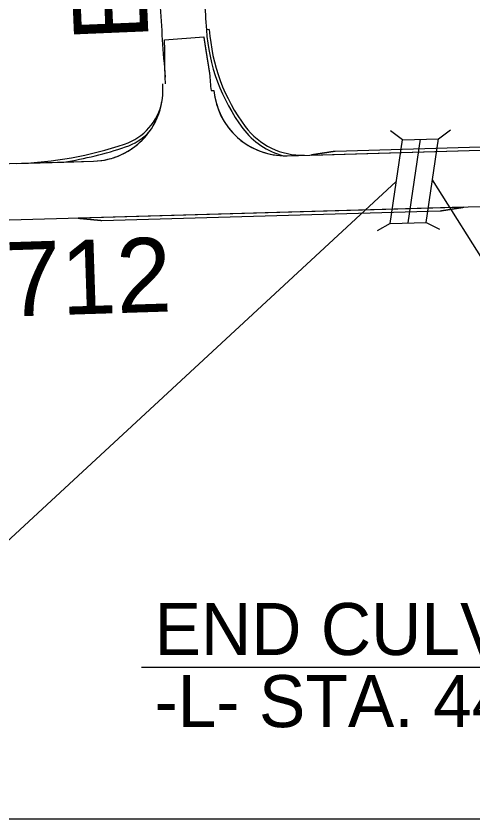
# Model space of a CAD drawing. Extents: x 1750553 to 1763838, y 734059 to 742526.
# Drawn here: x 1758820 to 1759127, y 736593 to 737133 of the extents above; entities that cross this region are included whole.
import ezdxf

# ---------------------------------------------------------------- set-up
doc = ezdxf.new("R2010")
doc.units = 0
for name, color, linetype in [('ENG SEALS CELL', 7, 'Continuous'), ('Old_Level_2', 7, 'Continuous'), ('Prop Drainage Structure Box Reinforced Concrete', 7, 'Continuous'), ('Sheet PE Seal Cell', 7, 'Continuous')]:
    doc.layers.add(name, color=color, linetype=linetype)

msp = doc.modelspace()

# ---------------------------------------------------------------- linework, layer by layer
at = {"layer": 'ENG SEALS CELL'}
msp.add_lwpolyline([(1758065.14, 737642.98), (1758094.96, 736592.98), (1759395.48, 736592.98), (1759372.29, 737409.84), (1759305.61, 737409.84), (1759305.61, 737642.98)], close=True, dxfattribs=at)
at = {"layer": 'Old_Level_2'}
for p, q in [((1758920.2, 737117), (1758946.57, 737118.84)), ((1758946.57, 737118.84), (1758946.53, 737118.84)), ((1758950.25, 737123.84), (1758948.26, 737123.71)), ((1758920.9, 737087.39), (1758920.53, 737091.81)), ((1758951.39, 737082.76), (1758953.38, 737082.93)), ((1759002.57, 737039.01), (1760207.16, 737073.22)), ((1759018.84, 737039.47), (1759254.68, 737046.17)), ((1759238.63, 737047.72), (1759034.78, 737041.93)), ((1759002.57, 737039.01), (1759014.23, 737039.34)), ((1757497.71, 736996.28), (1758872.43, 737035.32)), ((1760223.41, 737035.66), (1757498.72, 736958.29)), ((1758820.95, 737033.85), (1758852.5, 737034.75)), ((1758852.5, 737034.75), (1758872.43, 737035.32)), ((1758872.54, 737035.32), (1758872.64, 737035.32)), ((1759121.42, 737004.37), (1758862.05, 736997.01)), ((1758878.1, 736995.46), (1759105.48, 737001.92))]:
    msp.add_line(p, q, dxfattribs=at)
msp.add_lwpolyline([(1758920.2, 737117), (1758946.53, 737118.84), (1758946.57, 737118.84)], dxfattribs=at)
for centre, radius, start, end in [((1761377.64, 737289.03), 2465, 183.41974, 184.58755), ((1761377.64, 737289.03), 2435, 183.41974, 183.89301), ((1759072.97, 737132.19), 125, 183.893, 216.7448), ((1759072.97, 737132.19), 125, 183.893, 216.7448), ((1759072.97, 737132.19), 123, 183.893, 216.7448), ((1761377.64, 737289.03), 2435, 184.58904, 184.85937), ((1761377.64, 737289.03), 2435, 184.58904, 184.85937), ((1758871.07, 737083.3), 48, 271.6265, 4.6921), ((1759001.21, 737086.99), 48, 184.8594, 271.6265), ((1759001.21, 737086.99), 48, 184.8594, 268.5577), ((1758881.14, 737082.81), 38, 288.6709, 348.7824), ((1758871.07, 737083.3), 48, 323.5301, 350.5475), ((1758871.07, 737083.3), 48, 271.6265, 323.5301), ((1758881.14, 737082.81), 40, 288.6709, 315.4916), ((1758881.14, 737082.81), 40, 288.6709, 315.4916), ((1759012.87, 737087.32), 50, 216.7448, 255.0869), ((1759012.87, 737087.32), 50, 216.7448, 255.0869), ((1759012.87, 737087.32), 48, 216.7448, 271.6265), ((1758813.91, 737281.75), 248, 271.6265, 288.6709), ((1758813.91, 737281.75), 250, 278.8788, 288.6709), ((1758813.91, 737281.75), 250, 278.8788, 288.6709), ((1759001.21, 737086.99), 48, 268.5577, 271.6265)]:
    msp.add_arc(centre, radius, start, end, dxfattribs=at)
for points in [[(1758946.53, 737118.84), (1758946.63, 737118.17), (1758946.68, 737117.84), (1758946.73, 737117.51), (1758946.78, 737117.17), (1758946.84, 737116.84), (1758946.89, 737116.51), (1758946.94, 737116.17), (1758946.99, 737115.84), (1758947.04, 737115.51), (1758947.09, 737115.17), (1758947.15, 737114.84), (1758947.2, 737114.51), (1758947.25, 737114.17), (1758947.3, 737113.84), (1758947.35, 737113.51), (1758947.4, 737113.17), (1758947.46, 737112.84), (1758947.51, 737112.51), (1758947.56, 737112.18), (1758947.61, 737111.84), (1758947.67, 737111.51), (1758947.72, 737111.18), (1758947.77, 737110.84), (1758947.82, 737110.51), (1758947.87, 737110.18), (1758947.93, 737109.84), (1758947.98, 737109.51), (1758948.03, 737109.18), (1758948.08, 737108.85), (1758948.14, 737108.51), (1758948.19, 737108.18), (1758948.24, 737107.85), (1758948.3, 737107.51), (1758948.35, 737107.18), (1758948.4, 737106.85), (1758948.45, 737106.51), (1758948.51, 737106.18), (1758948.56, 737105.85), (1758948.61, 737105.52), (1758948.67, 737105.18), (1758948.72, 737104.85), (1758948.77, 737104.52), (1758948.83, 737104.19), (1758948.88, 737103.85), (1758948.93, 737103.52), (1758948.99, 737103.19), (1758949.04, 737102.85), (1758949.09, 737102.52), (1758949.15, 737102.19), (1758949.2, 737101.86), (1758949.25, 737101.52), (1758949.31, 737101.19), (1758949.36, 737100.86), (1758949.41, 737100.52), (1758949.47, 737100.19), (1758949.52, 737099.86), (1758949.57, 737099.53), (1758949.63, 737099.19), (1758949.68, 737098.86), (1758949.74, 737098.53), (1758949.79, 737098.2), (1758949.84, 737097.86), (1758949.9, 737097.53), (1758949.95, 737097.2), (1758950.01, 737096.87), (1758950.06, 737096.53), (1758950.12, 737096.2), (1758950.17, 737095.87), (1758950.22, 737095.54), (1758950.28, 737095.2), (1758950.33, 737094.87), (1758950.39, 737094.54), (1758950.44, 737094.21)], [(1758946.53, 737118.84), (1758946.63, 737118.17), (1758946.68, 737117.84), (1758946.73, 737117.51), (1758946.78, 737117.17), (1758946.84, 737116.84), (1758946.89, 737116.51), (1758946.94, 737116.17), (1758946.99, 737115.84), (1758947.04, 737115.51), (1758947.09, 737115.17), (1758947.15, 737114.84), (1758947.2, 737114.51), (1758947.25, 737114.17), (1758947.3, 737113.84), (1758947.35, 737113.51), (1758947.4, 737113.17), (1758947.46, 737112.84), (1758947.51, 737112.51), (1758947.56, 737112.18), (1758947.61, 737111.84), (1758947.67, 737111.51), (1758947.72, 737111.18), (1758947.77, 737110.84), (1758947.8, 737110.62)], [(1758920.53, 737091.81), (1758920.53, 737092.15), (1758920.52, 737092.49), (1758920.52, 737092.83), (1758920.51, 737093.17), (1758920.5, 737093.51), (1758920.5, 737093.85), (1758920.49, 737094.19), (1758920.49, 737094.53), (1758920.48, 737094.87), (1758920.48, 737095.21), (1758920.47, 737095.55), (1758920.46, 737095.89), (1758920.46, 737096.23), (1758920.45, 737096.57), (1758920.45, 737096.91), (1758920.44, 737097.25), (1758920.44, 737097.59), (1758920.43, 737097.93), (1758920.43, 737098.27), (1758920.42, 737098.62), (1758920.42, 737098.96), (1758920.41, 737099.3), (1758920.4, 737099.64), (1758920.4, 737099.98), (1758920.39, 737100.32), (1758920.39, 737100.66), (1758920.38, 737101), (1758920.38, 737101.34), (1758920.37, 737101.68), (1758920.37, 737102.02), (1758920.37, 737102.36), (1758920.36, 737102.7), (1758920.36, 737103.04), (1758920.35, 737103.38), (1758920.35, 737103.72), (1758920.34, 737104.06), (1758920.34, 737104.4), (1758920.33, 737104.74), (1758920.33, 737105.08), (1758920.32, 737105.42), (1758920.32, 737105.76), (1758920.32, 737106.1), (1758920.31, 737106.44), (1758920.31, 737106.79), (1758920.3, 737107.13), (1758920.3, 737107.47), (1758920.3, 737107.81), (1758920.29, 737108.15), (1758920.29, 737108.49), (1758920.28, 737108.83), (1758920.28, 737109.17), (1758920.28, 737109.51), (1758920.27, 737109.85), (1758920.27, 737110.19), (1758920.27, 737110.53), (1758920.26, 737110.87), (1758920.26, 737111.21), (1758920.25, 737111.55), (1758920.25, 737111.89), (1758920.25, 737112.23), (1758920.24, 737112.57), (1758920.24, 737112.91), (1758920.24, 737113.25), (1758920.23, 737113.59), (1758920.23, 737113.93), (1758920.23, 737114.27), (1758920.23, 737114.61), (1758920.22, 737114.95), (1758920.22, 737115.29), (1758920.22, 737115.64), (1758920.21, 737115.98), (1758920.21, 737116.32), (1758920.2, 737117)], [(1758920.29, 737108.6), (1758920.28, 737108.83), (1758920.28, 737109.17), (1758920.28, 737109.51), (1758920.27, 737109.85), (1758920.27, 737110.19), (1758920.27, 737110.53), (1758920.26, 737110.87), (1758920.26, 737111.21), (1758920.25, 737111.55), (1758920.25, 737111.89), (1758920.25, 737112.23), (1758920.24, 737112.57), (1758920.24, 737112.91), (1758920.24, 737113.25), (1758920.23, 737113.59), (1758920.23, 737113.93), (1758920.23, 737114.27), (1758920.23, 737114.61), (1758920.22, 737114.95), (1758920.22, 737115.29), (1758920.22, 737115.64), (1758920.21, 737115.98), (1758920.21, 737116.32), (1758920.2, 737117)], [(1758920.4, 737100.2), (1758920.39, 737100.32), (1758920.39, 737100.66), (1758920.38, 737101), (1758920.38, 737101.34), (1758920.37, 737101.68), (1758920.37, 737102.02), (1758920.37, 737102.36), (1758920.36, 737102.7), (1758920.36, 737103.04), (1758920.35, 737103.38), (1758920.35, 737103.72), (1758920.34, 737104.06), (1758920.34, 737104.4), (1758920.33, 737104.74), (1758920.33, 737105.08), (1758920.32, 737105.42), (1758920.32, 737105.76), (1758920.32, 737106.1), (1758920.31, 737106.44), (1758920.31, 737106.79), (1758920.3, 737107.13), (1758920.3, 737107.47), (1758920.3, 737107.81), (1758920.29, 737108.15), (1758920.29, 737108.49), (1758920.29, 737108.6)], [(1758947.8, 737110.62), (1758947.82, 737110.51), (1758947.87, 737110.18), (1758947.93, 737109.84), (1758947.98, 737109.51), (1758948.03, 737109.18), (1758948.08, 737108.85), (1758948.14, 737108.51), (1758948.19, 737108.18), (1758948.24, 737107.85), (1758948.3, 737107.51), (1758948.35, 737107.18), (1758948.4, 737106.85), (1758948.45, 737106.51), (1758948.51, 737106.18), (1758948.56, 737105.85), (1758948.61, 737105.52), (1758948.67, 737105.18), (1758948.72, 737104.85), (1758948.77, 737104.52), (1758948.83, 737104.19), (1758948.88, 737103.85), (1758948.93, 737103.52), (1758948.99, 737103.19), (1758949.04, 737102.85), (1758949.09, 737102.52), (1758949.11, 737102.41)], [(1758920.53, 737091.87), (1758920.53, 737092.15), (1758920.52, 737092.49), (1758920.52, 737092.83), (1758920.51, 737093.17), (1758920.5, 737093.51), (1758920.5, 737093.85), (1758920.49, 737094.19), (1758920.49, 737094.53), (1758920.48, 737094.87), (1758920.48, 737095.21), (1758920.47, 737095.55), (1758920.46, 737095.89), (1758920.46, 737096.23), (1758920.45, 737096.57), (1758920.45, 737096.91), (1758920.44, 737097.25), (1758920.44, 737097.59), (1758920.43, 737097.93), (1758920.43, 737098.27), (1758920.42, 737098.62), (1758920.42, 737098.96), (1758920.41, 737099.3), (1758920.4, 737099.64), (1758920.4, 737099.98), (1758920.4, 737100.2)], [(1758949.11, 737102.41), (1758949.15, 737102.19), (1758949.2, 737101.86), (1758949.25, 737101.52), (1758949.31, 737101.19), (1758949.36, 737100.86), (1758949.41, 737100.52), (1758949.47, 737100.19), (1758949.52, 737099.86), (1758949.57, 737099.53), (1758949.63, 737099.19), (1758949.68, 737098.86), (1758949.74, 737098.53), (1758949.79, 737098.2), (1758949.84, 737097.86), (1758949.9, 737097.53), (1758949.95, 737097.2), (1758950.01, 737096.87), (1758950.06, 737096.53), (1758950.12, 737096.2), (1758950.17, 737095.87), (1758950.22, 737095.54), (1758950.28, 737095.2), (1758950.33, 737094.87), (1758950.39, 737094.54), (1758950.44, 737094.21)], [(1759024.15, 737040.29), (1759024.01, 737040.27), (1759023.79, 737040.24), (1759023.58, 737040.2), (1759023.36, 737040.17), (1759023.15, 737040.14), (1759022.93, 737040.1), (1759022.72, 737040.07), (1759022.5, 737040.04), (1759022.29, 737040), (1759022.07, 737039.97), (1759021.85, 737039.94), (1759021.64, 737039.9), (1759021.42, 737039.87), (1759021.21, 737039.84), (1759020.99, 737039.8), (1759020.78, 737039.77), (1759020.56, 737039.74), (1759020.35, 737039.71), (1759020.13, 737039.67), (1759019.92, 737039.64), (1759019.7, 737039.61), (1759019.49, 737039.57), (1759019.27, 737039.54), (1759018.84, 737039.47)], [(1759029.46, 737041.11), (1759029.39, 737041.1), (1759029.18, 737041.06), (1759028.96, 737041.03), (1759028.75, 737041), (1759028.53, 737040.97), (1759028.32, 737040.93), (1759028.1, 737040.9), (1759027.88, 737040.87), (1759027.67, 737040.83), (1759027.45, 737040.8), (1759027.24, 737040.77), (1759027.02, 737040.73), (1759026.81, 737040.7), (1759026.59, 737040.67), (1759026.38, 737040.63), (1759026.16, 737040.6), (1759025.95, 737040.57), (1759025.73, 737040.53), (1759025.52, 737040.5), (1759025.3, 737040.47), (1759025.09, 737040.43), (1759024.87, 737040.4), (1759024.65, 737040.37), (1759024.44, 737040.34), (1759024.22, 737040.3), (1759024.15, 737040.29)], [(1759034.78, 737041.93), (1759034.56, 737041.89), (1759034.35, 737041.86), (1759034.13, 737041.83), (1759033.91, 737041.79), (1759033.7, 737041.76), (1759033.48, 737041.73), (1759033.27, 737041.69), (1759033.05, 737041.66), (1759032.84, 737041.63), (1759032.62, 737041.6), (1759032.41, 737041.56), (1759032.19, 737041.53), (1759031.98, 737041.5), (1759031.76, 737041.46), (1759031.55, 737041.43), (1759031.33, 737041.4), (1759031.12, 737041.36), (1759030.9, 737041.33), (1759030.68, 737041.3), (1759030.47, 737041.26), (1759030.25, 737041.23), (1759030.04, 737041.2), (1759029.82, 737041.16), (1759029.61, 737041.13), (1759029.46, 737041.11)], [(1759105.48, 737001.92), (1759105.7, 737001.95), (1759105.91, 737001.98), (1759106.13, 737002.02), (1759106.34, 737002.05), (1759106.56, 737002.08), (1759106.77, 737002.12), (1759106.99, 737002.15), (1759107.2, 737002.18), (1759107.42, 737002.22), (1759107.63, 737002.25), (1759107.85, 737002.28), (1759108.06, 737002.32), (1759108.28, 737002.35), (1759108.5, 737002.38), (1759108.71, 737002.41), (1759108.93, 737002.45), (1759109.14, 737002.48), (1759109.36, 737002.51), (1759109.57, 737002.55), (1759109.79, 737002.58), (1759110, 737002.61), (1759110.22, 737002.65), (1759110.43, 737002.68), (1759110.65, 737002.71), (1759110.79, 737002.74)], [(1759110.79, 737002.74), (1759110.86, 737002.75), (1759111.08, 737002.78), (1759111.3, 737002.81), (1759111.51, 737002.85), (1759111.73, 737002.88), (1759111.94, 737002.91), (1759112.16, 737002.95), (1759112.37, 737002.98), (1759112.59, 737003.01), (1759112.8, 737003.04), (1759113.02, 737003.08), (1759113.23, 737003.11), (1759113.45, 737003.14), (1759113.66, 737003.18), (1759113.88, 737003.21), (1759114.09, 737003.24), (1759114.31, 737003.28), (1759114.53, 737003.31), (1759114.74, 737003.34), (1759114.96, 737003.38), (1759115.17, 737003.41), (1759115.39, 737003.44), (1759115.6, 737003.48), (1759115.82, 737003.51), (1759116.03, 737003.54), (1759116.1, 737003.55)], [(1759116.1, 737003.55), (1759116.25, 737003.58), (1759116.46, 737003.61), (1759116.68, 737003.64), (1759116.89, 737003.67), (1759117.11, 737003.71), (1759117.33, 737003.74), (1759117.54, 737003.77), (1759117.76, 737003.81), (1759117.97, 737003.84), (1759118.19, 737003.87), (1759118.4, 737003.91), (1759118.62, 737003.94), (1759118.83, 737003.97), (1759119.05, 737004.01), (1759119.26, 737004.04), (1759119.48, 737004.07), (1759119.69, 737004.11), (1759119.91, 737004.14), (1759120.13, 737004.17), (1759120.34, 737004.21), (1759120.56, 737004.24), (1759120.77, 737004.27), (1759120.99, 737004.3), (1759121.42, 737004.37)]]:
    msp.add_spline(points, degree=3, dxfattribs=at)
for points in [[(1758862.05, 736997.01), (1758862.2, 736996.99), (1758862.34, 736996.98), (1758862.49, 736996.96), (1758862.56, 736996.96), (1758862.63, 736996.95), (1758862.7, 736996.94), (1758862.77, 736996.94), (1758862.85, 736996.93), (1758862.92, 736996.92), (1758862.99, 736996.92), (1758863.06, 736996.91), (1758863.14, 736996.9), (1758863.21, 736996.89), (1758863.28, 736996.89), (1758863.35, 736996.88), (1758863.43, 736996.87), (1758863.5, 736996.87), (1758863.57, 736996.86), (1758863.64, 736996.85), (1758863.71, 736996.85), (1758863.79, 736996.84), (1758863.86, 736996.83), (1758863.93, 736996.82), (1758864, 736996.82), (1758864.08, 736996.81), (1758864.15, 736996.8), (1758864.22, 736996.8), (1758864.29, 736996.79), (1758864.37, 736996.78), (1758864.44, 736996.78), (1758864.51, 736996.77), (1758864.58, 736996.76), (1758864.65, 736996.76), (1758864.73, 736996.75), (1758864.8, 736996.74), (1758864.87, 736996.73), (1758864.94, 736996.73), (1758865.02, 736996.72), (1758865.09, 736996.71), (1758865.16, 736996.71), (1758865.23, 736996.7), (1758865.31, 736996.69), (1758865.38, 736996.69), (1758865.45, 736996.68), (1758865.52, 736996.67), (1758865.59, 736996.66), (1758865.67, 736996.66), (1758865.74, 736996.65), (1758865.81, 736996.64), (1758865.88, 736996.64), (1758865.96, 736996.63), (1758866.03, 736996.62), (1758866.1, 736996.62), (1758866.17, 736996.61), (1758866.25, 736996.6), (1758866.32, 736996.6), (1758866.39, 736996.59), (1758866.46, 736996.58), (1758866.53, 736996.57), (1758866.61, 736996.57), (1758866.68, 736996.56), (1758866.75, 736996.55), (1758866.82, 736996.55), (1758866.9, 736996.54), (1758866.97, 736996.53), (1758867.04, 736996.53), (1758867.11, 736996.52), (1758867.18, 736996.51), (1758867.26, 736996.5), (1758867.31, 736996.5), (1758867.35, 736996.5), (1758867.4, 736996.49)], [(1758867.4, 736996.49), (1758867.43, 736996.49), (1758867.45, 736996.49), (1758867.47, 736996.48), (1758867.55, 736996.48), (1758867.62, 736996.47), (1758867.69, 736996.46), (1758867.76, 736996.46), (1758867.84, 736996.45), (1758867.91, 736996.44), (1758867.98, 736996.44), (1758868.05, 736996.43), (1758868.12, 736996.42), (1758868.2, 736996.41), (1758868.27, 736996.41), (1758868.34, 736996.4), (1758868.41, 736996.39), (1758868.49, 736996.39), (1758868.56, 736996.38), (1758868.63, 736996.37), (1758868.7, 736996.37), (1758868.78, 736996.36), (1758868.85, 736996.35), (1758868.92, 736996.34), (1758868.99, 736996.34), (1758869.06, 736996.33), (1758869.14, 736996.32), (1758869.21, 736996.32), (1758869.28, 736996.31), (1758869.35, 736996.3), (1758869.43, 736996.3), (1758869.5, 736996.29), (1758869.57, 736996.28), (1758869.64, 736996.28), (1758869.72, 736996.27), (1758869.79, 736996.26), (1758869.86, 736996.25), (1758869.93, 736996.25), (1758870, 736996.24), (1758870.08, 736996.23), (1758870.15, 736996.23), (1758870.22, 736996.22), (1758870.29, 736996.21), (1758870.37, 736996.21), (1758870.44, 736996.2), (1758870.51, 736996.19), (1758870.58, 736996.18), (1758870.66, 736996.18), (1758870.73, 736996.17), (1758870.8, 736996.16), (1758870.87, 736996.16), (1758870.94, 736996.15), (1758871.02, 736996.14), (1758871.09, 736996.14), (1758871.16, 736996.13), (1758871.23, 736996.12), (1758871.31, 736996.12), (1758871.38, 736996.11), (1758871.45, 736996.1), (1758871.52, 736996.09), (1758871.6, 736996.09), (1758871.67, 736996.08), (1758871.74, 736996.07), (1758871.81, 736996.07), (1758871.88, 736996.06), (1758871.96, 736996.05), (1758872.03, 736996.05), (1758872.1, 736996.04), (1758872.17, 736996.03), (1758872.25, 736996.02), (1758872.32, 736996.02), (1758872.39, 736996.01), (1758872.46, 736996), (1758872.54, 736996), (1758872.61, 736995.99), (1758872.68, 736995.98), (1758872.7, 736995.98), (1758872.73, 736995.98), (1758872.75, 736995.98)], [(1758872.75, 736995.98), (1758872.8, 736995.97), (1758872.85, 736995.97), (1758872.9, 736995.96), (1758872.97, 736995.95), (1758873.04, 736995.95), (1758873.11, 736995.94), (1758873.19, 736995.93), (1758873.26, 736995.93), (1758873.33, 736995.92), (1758873.4, 736995.91), (1758873.47, 736995.91), (1758873.55, 736995.9), (1758873.62, 736995.89), (1758873.69, 736995.89), (1758873.76, 736995.88), (1758873.84, 736995.87), (1758873.91, 736995.86), (1758873.98, 736995.86), (1758874.05, 736995.85), (1758874.13, 736995.84), (1758874.2, 736995.84), (1758874.27, 736995.83), (1758874.34, 736995.82), (1758874.41, 736995.82), (1758874.49, 736995.81), (1758874.56, 736995.8), (1758874.63, 736995.79), (1758874.7, 736995.79), (1758874.78, 736995.78), (1758874.85, 736995.77), (1758874.92, 736995.77), (1758874.99, 736995.76), (1758875.07, 736995.75), (1758875.14, 736995.75), (1758875.21, 736995.74), (1758875.28, 736995.73), (1758875.35, 736995.73), (1758875.43, 736995.72), (1758875.5, 736995.71), (1758875.57, 736995.7), (1758875.64, 736995.7), (1758875.72, 736995.69), (1758875.79, 736995.68), (1758875.86, 736995.68), (1758875.93, 736995.67), (1758876.01, 736995.66), (1758876.08, 736995.66), (1758876.15, 736995.65), (1758876.22, 736995.64), (1758876.29, 736995.63), (1758876.37, 736995.63), (1758876.44, 736995.62), (1758876.51, 736995.61), (1758876.58, 736995.61), (1758876.66, 736995.6), (1758876.73, 736995.59), (1758876.8, 736995.59), (1758876.87, 736995.58), (1758876.95, 736995.57), (1758877.02, 736995.57), (1758877.09, 736995.56), (1758877.16, 736995.55), (1758877.23, 736995.54), (1758877.31, 736995.54), (1758877.38, 736995.53), (1758877.45, 736995.52), (1758877.52, 736995.52), (1758877.6, 736995.51), (1758877.67, 736995.5), (1758877.74, 736995.5), (1758877.81, 736995.49), (1758877.89, 736995.48), (1758877.96, 736995.47), (1758878.03, 736995.47), (1758878.1, 736995.46)]]:
    msp.add_open_spline(points, degree=3, dxfattribs=at)
at = {"layer": 'Prop Drainage Structure Box Reinforced Concrete'}
for p, q in [((1759080.06, 737049.72), (1759072, 737055.64)), ((1759104.42, 737050.41), (1759112.48, 737056.32)), ((1759071.78, 736993.46), (1759080.06, 737049.72)), ((1759080.06, 737049.72), (1759104.42, 737050.41)), ((1759083.96, 736993.8), (1759092.24, 737050.06)), ((1759096.14, 736994.15), (1759104.42, 737050.41)), ((1759071.78, 736993.46), (1759063.08, 736988.52)), ((1759071.78, 736993.46), (1759096.14, 736994.15)), ((1759096.14, 736994.15), (1759105, 736989.53))]:
    msp.add_line(p, q, dxfattribs=at)
at = {"layer": 'Sheet PE Seal Cell'}
for p, q in [((1759075.92, 737021.59), (1758754.14, 736723.95)), ((1759100.09, 737022.85), (1759305.41, 736695.13)), ((1758904.66, 736695.13), (1759305.41, 736695.13))]:
    msp.add_line(p, q, dxfattribs=at)
msp.add_lwpolyline([(1758065.14, 737642.98), (1758094.96, 736592.98), (1759395.48, 736592.98), (1759365.67, 737642.98)], close=True, dxfattribs=at)

# ---------------------------------------------------------------- texts
for s, height, rotation, p in [('BANK ST', 50, 92.4329, (1758909.45, 737117.2)), ('SR 1712', 50, 1.8239, (1758665.47, 736926.03)), ('END CULVERT', 35, 360, (1758913.39, 736703.21)), ('-L- STA. 44+17.19', 35, 360, (1758913.39, 736654.71))]:
    msp.add_text(s, height=height, rotation=rotation, dxfattribs=at).set_placement(p)

doc.saveas('drawing.dxf')
